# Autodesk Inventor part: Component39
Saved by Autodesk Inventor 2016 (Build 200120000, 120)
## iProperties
Created: 2016-09
Part Number: Component39
Material: Generic
Document SubType Name: Modeling
Designer: Administrator
Appearance: Generic
Author: Administrator
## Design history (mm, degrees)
feature "Body1"
body "Solid1"
